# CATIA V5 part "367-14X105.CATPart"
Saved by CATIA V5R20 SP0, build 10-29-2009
Part number: 367-14X105
Definition: NONE
Nomenclature: 367-14X105
Source: Unknown
Description: 367-14X105
Bounding box of the stored display mesh (mm): x 0 to 105, y -14 to 14, z -14 to 14
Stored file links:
  C:\Users\Utente\Desktop\IO LAVORO\3D X SITO CF\X SITO\PLASTICA\3D files 367\367-14X105.CATPart
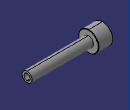
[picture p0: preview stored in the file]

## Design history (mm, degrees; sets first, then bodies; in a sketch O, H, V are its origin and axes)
Body1 "367-14X105" (main body)
  Solid1: solid without history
